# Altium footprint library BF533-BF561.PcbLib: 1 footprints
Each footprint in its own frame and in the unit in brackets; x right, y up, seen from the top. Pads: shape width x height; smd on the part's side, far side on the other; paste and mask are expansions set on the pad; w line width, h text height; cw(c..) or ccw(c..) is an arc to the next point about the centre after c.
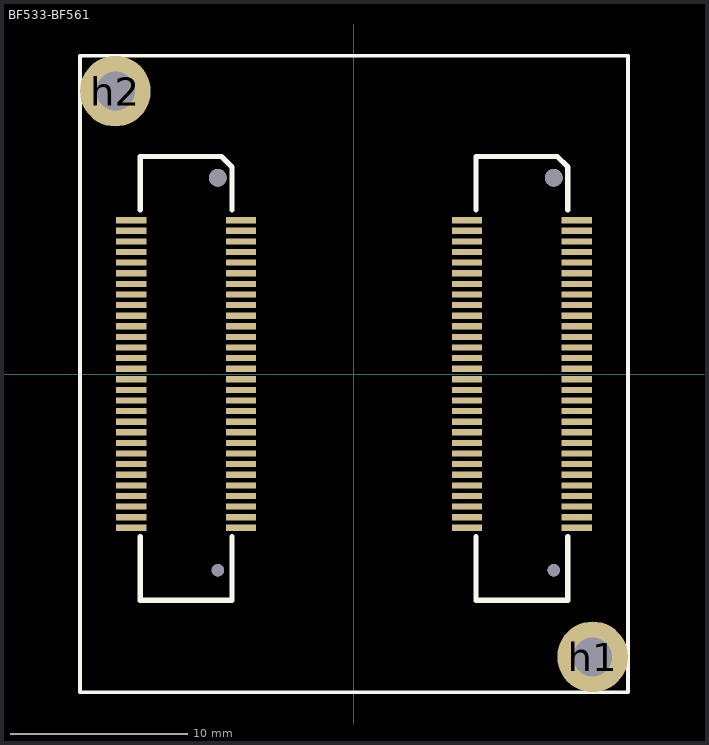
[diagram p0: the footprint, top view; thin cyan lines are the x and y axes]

## BF533-BF561 [mm] "Blackfin Board with Harwin Connectors"
height 5
pads (126):
  rect 1.7x0.35 smd paste-0.025: 1(-6.4,8.7) 2(-6.4,8.1) 3(-6.4,7.5) 4(-6.4,6.9) 5(-6.4,6.3) 6(-6.4,5.7) 7(-6.4,5.1) 8(-6.4,4.5) 9(-6.4,3.9) 10(-6.4,3.3) 11(-6.4,2.7) 12(-6.4,2.1) 13(-6.4,1.5) 14(-6.4,0.9) 15(-6.4,0.3) 16(-6.4,-0.3) 17(-6.4,-0.9) 18(-6.4,-1.5) 19(-6.4,-2.1) 20(-6.4,-2.7) 21(-6.4,-3.3) 22(-6.4,-3.9) 23(-6.4,-4.5) 24(-6.4,-5.1) 25(-6.4,-5.7) 26(-6.4,-6.3) 27(-6.4,-6.9) 28(-6.4,-7.5) 29(-6.4,-8.1) 30(-6.4,-8.7) 31(-12.6,-8.7) 32(-12.6,-8.1) 33(-12.6,-7.5) 34(-12.6,-6.9) 35(-12.6,-6.3) 36(-12.6,-5.7) 37(-12.6,-5.1) 38(-12.6,-4.5) 39(-12.6,-3.9) 40(-12.6,-3.3) 41(-12.6,-2.7) 42(-12.6,-2.1) 43(-12.6,-1.5) 44(-12.6,-0.9) 45(-12.6,-0.3) 46(-12.6,0.3) 47(-12.6,0.9) 48(-12.6,1.5) 49(-12.6,2.1) 50(-12.6,2.7) 51(-12.6,3.3) 52(-12.6,3.9) 53(-12.6,4.5) 54(-12.6,5.1) 55(-12.6,5.7) 56(-12.6,6.3) 57(-12.6,6.9) 58(-12.6,7.5) 59(-12.6,8.1) 60(-12.6,8.7) 61(12.6,8.7) 62(12.6,8.1) 63(12.6,7.5) 64(12.6,6.9) 65(12.6,6.3) 66(12.6,5.7) 67(12.6,5.1) 68(12.6,4.5) 69(12.6,3.9) 70(12.6,3.3) 71(12.6,2.7) 72(12.6,2.1) 73(12.6,1.5) 74(12.6,0.9) 75(12.6,0.3) 76(12.6,-0.3) 77(12.6,-0.9) 78(12.6,-1.5) 79(12.6,-2.1) 80(12.6,-2.7) 81(12.6,-3.3) 82(12.6,-3.9) 83(12.6,-4.5) 84(12.6,-5.1) 85(12.6,-5.7) 86(12.6,-6.3) 87(12.6,-6.9) 88(12.6,-7.5) 89(12.6,-8.1) 90(12.6,-8.7) 91(6.4,-8.7) 92(6.4,-8.1) 93(6.4,-7.5) 94(6.4,-6.9) 95(6.4,-6.3) 96(6.4,-5.7) 97(6.4,-5.1) 98(6.4,-4.5) 99(6.4,-3.9) 100(6.4,-3.3) 101(6.4,-2.7) 102(6.4,-2.1) 103(6.4,-1.5) 104(6.4,-0.9) 105(6.4,-0.3) 106(6.4,0.3) 107(6.4,0.9) 108(6.4,1.5) 109(6.4,2.1) 110(6.4,2.7) 111(6.4,3.3) 112(6.4,3.9) 113(6.4,4.5) 114(6.4,5.1) 115(6.4,5.7) 116(6.4,6.3) 117(6.4,6.9) 118(6.4,7.5) 119(6.4,8.1) 120(6.4,8.7)
  round 4 / inner round 2.5 / far side round 4 hole 2.2: h1(13.5,-16) h2(-13.5,16)
  round 1 hole 1 unplated: Hole1(-7.7,11.1) Hole1(11.3,11.1)
  round 0.7 hole 0.7 unplated: Hole2(-7.7,-11.1) Hole2(11.3,-11.1)
Top Overlay:
  lines w0.2: -15.5,-18 15.5,-18 15.5,18 -15.5,18 -15.5,-18
  lines w0.3: -12.1,-9.2 -12.1,-12.8 -6.9,-12.8 -6.9,-9.2 ; -12.1,9.3 -12.1,12.3 -7.5,12.3 -6.9,11.7 -6.9,9.3 ; 6.9,-9.2 6.9,-12.8 12.1,-12.8 12.1,-9.2 ; 6.9,9.3 6.9,12.3 11.5,12.3 12.1,11.7 12.1,9.3
3D body: height 2.2, standoff 0.1, extent 7.925,8.575 8.125,8.825
3D body: height 2.2, standoff 0.1, extent 7.925,7.975 8.125,8.225
3D body: height 2.2, standoff 0.1, extent 7.925,6.775 8.125,7.025
3D body: height 2.2, standoff 0.1, extent 7.925,7.375 8.125,7.625
3D body: height 2.2, standoff 0.1, extent 7.925,4.975 8.125,5.225
3D body: height 2.2, standoff 0.1, extent 7.925,4.375 8.125,4.625
3D body: height 2.2, standoff 0.1, extent 7.925,5.575 8.125,5.825
3D body: height 2.2, standoff 0.1, extent 7.925,6.175 8.125,6.425
3D body: height 2.2, standoff 0.1, extent 7.925,2.575 8.125,2.825
3D body: height 2.2, standoff 0.1, extent 7.925,1.975 8.125,2.225
3D body: height 2.2, standoff 0.1, extent 7.925,3.175 8.125,3.425
3D body: height 2.2, standoff 0.1, extent 7.925,3.775 8.125,4.025
3D body: height 2.2, standoff 0.1, extent 7.925,0.175 8.125,0.425
3D body: height 2.2, standoff 0.1, extent 7.925,-0.425 8.125,-0.175
3D body: height 2.2, standoff 0.1, extent 7.925,0.775 8.125,1.025
3D body: height 2.2, standoff 0.1, extent 7.925,1.375 8.125,1.625
3D body: height 2.2, standoff 0.1, extent 7.925,-2.225 8.125,-1.975
3D body: height 2.2, standoff 0.1, extent 7.925,-2.825 8.125,-2.575
3D body: height 2.2, standoff 0.1, extent 7.925,-1.625 8.125,-1.375
3D body: height 2.2, standoff 0.1, extent 7.925,-1.025 8.125,-0.775
3D body: height 2.2, standoff 0.1, extent 7.925,-4.625 8.125,-4.375
3D body: height 2.2, standoff 0.1, extent 7.925,-5.225 8.125,-4.975
3D body: height 2.2, standoff 0.1, extent 7.925,-4.025 8.125,-3.775
3D body: height 2.2, standoff 0.1, extent 7.925,-3.425 8.125,-3.175
3D body: height 2.2, standoff 0.1, extent 7.925,-7.025 8.125,-6.775
3D body: height 2.2, standoff 0.1, extent 7.925,-7.625 8.125,-7.375
3D body: height 2.2, standoff 0.1, extent 7.925,-6.425 8.125,-6.175
3D body: height 2.2, standoff 0.1, extent 7.925,-5.825 8.125,-5.575
3D body: height 2.2, standoff 0.1, extent 7.925,-8.825 8.125,-8.575
3D body: height 0.2, standoff 0, extent 6,-8.825 8.125,-8.575
3D body: height 2.2, standoff 0.1, extent 7.925,-8.225 8.125,-7.975
3D body: height 0.2, standoff 0, extent 6,-8.225 8.125,-7.975
3D body: height 0.2, standoff 0, extent 6,-7.625 8.125,-7.375
3D body: height 0.2, standoff 0, extent 6,-7.025 8.125,-6.775
3D body: height 0.2, standoff 0, extent 6,-6.425 8.125,-6.175
3D body: height 0.2, standoff 0, extent 6,-3.425 8.125,-3.175
3D body: height 0.2, standoff 0, extent 6,-4.025 8.125,-3.775
3D body: height 0.2, standoff 0, extent 6,-4.625 8.125,-4.375
3D body: height 0.2, standoff 0, extent 6,-5.225 8.125,-4.975
3D body: height 0.2, standoff 0, extent 6,-5.825 8.125,-5.575
3D body: height 0.2, standoff 0, extent 6,-0.425 8.125,-0.175
3D body: height 0.2, standoff 0, extent 6,-1.025 8.125,-0.775
3D body: height 0.2, standoff 0, extent 6,-1.625 8.125,-1.375
3D body: height 0.2, standoff 0, extent 6,-2.225 8.125,-1.975
3D body: height 0.2, standoff 0, extent 6,-2.825 8.125,-2.575
3D body: height 0.2, standoff 0, extent 6,2.575 8.125,2.825
3D body: height 0.2, standoff 0, extent 6,1.975 8.125,2.225
3D body: height 0.2, standoff 0, extent 6,1.375 8.125,1.625
3D body: height 0.2, standoff 0, extent 6,0.775 8.125,1.025
3D body: height 0.2, standoff 0, extent 6,0.175 8.125,0.425
3D body: height 0.2, standoff 0, extent 6,5.575 8.125,5.825
3D body: height 0.2, standoff 0, extent 6,4.975 8.125,5.225
3D body: height 0.2, standoff 0, extent 6,4.375 8.125,4.625
3D body: height 0.2, standoff 0, extent 6,3.775 8.125,4.025
3D body: height 0.2, standoff 0, extent 6,3.175 8.125,3.425
3D body: height 0.2, standoff 0, extent 6,8.575 8.125,8.825
3D body: height 0.2, standoff 0, extent 6,7.975 8.125,8.225
3D body: height 0.2, standoff 0, extent 6,7.375 8.125,7.625
3D body: height 0.2, standoff 0, extent 6,6.775 8.125,7.025
3D body: height 0.2, standoff 0, extent 6,6.175 8.125,6.425
3D body: height 0.5, standoff 0.1, extent 6.9,-12.8 12.1,12.3
3D body: height 2.25, standoff 0.1, extent 7.95,-9.65 11.05,9.65
3D body: height 2.25, standoff 0.1, extent 6.9,-12.8 12.1,12.3
3D body: height 0.2, standoff 0, extent 10.875,-6.425 13,-6.175
3D body: height 0.2, standoff 0, extent 10.875,-7.025 13,-6.775
3D body: height 0.2, standoff 0, extent 10.875,-7.625 13,-7.375
3D body: height 0.2, standoff 0, extent 10.875,-8.225 13,-7.975
3D body: height 0.2, standoff 0, extent 10.875,-8.825 13,-8.575
3D body: height 0.2, standoff 0, extent 10.875,-3.425 13,-3.175
3D body: height 0.2, standoff 0, extent 10.875,-4.025 13,-3.775
3D body: height 0.2, standoff 0, extent 10.875,-4.625 13,-4.375
3D body: height 0.2, standoff 0, extent 10.875,-5.225 13,-4.975
3D body: height 0.2, standoff 0, extent 10.875,-5.825 13,-5.575
3D body: height 0.2, standoff 0, extent 10.875,-0.425 13,-0.175
3D body: height 0.2, standoff 0, extent 10.875,-1.025 13,-0.775
3D body: height 0.2, standoff 0, extent 10.875,-1.625 13,-1.375
3D body: height 0.2, standoff 0, extent 10.875,-2.225 13,-1.975
3D body: height 0.2, standoff 0, extent 10.875,-2.825 13,-2.575
3D body: height 0.2, standoff 0, extent 10.875,2.575 13,2.825
3D body: height 0.2, standoff 0, extent 10.875,1.975 13,2.225
3D body: height 0.2, standoff 0, extent 10.875,1.375 13,1.625
3D body: height 0.2, standoff 0, extent 10.875,0.775 13,1.025
3D body: height 0.2, standoff 0, extent 10.875,0.175 13,0.425
3D body: height 0.2, standoff 0, extent 10.875,5.575 13,5.825
3D body: height 0.2, standoff 0, extent 10.875,4.975 13,5.225
3D body: height 0.2, standoff 0, extent 10.875,4.375 13,4.625
3D body: height 0.2, standoff 0, extent 10.875,3.775 13,4.025
3D body: height 0.2, standoff 0, extent 10.875,3.175 13,3.425
3D body: height 0.2, standoff 0, extent 10.875,6.175 13,6.425
3D body: height 0.2, standoff 0, extent 10.875,6.775 13,7.025
3D body: height 0.2, standoff 0, extent 10.875,7.375 13,7.625
3D body: height 0.2, standoff 0, extent 10.875,7.975 13,8.225
3D body: height 0.25, standoff -0.75, extent 10.852,10.654 11.75,11.55
3D body: height 0.25, standoff -0.75, extent 11.001,-11.398 11.6,-10.8
3D body: height 2.2, standoff 0.1, extent 10.875,7.975 11.075,8.225
3D body: height 0.2, standoff 0, extent 10.875,8.575 13,8.825
3D body: height 2.2, standoff 0.1, extent 10.875,8.575 11.075,8.825
3D body: height 2.2, standoff 0.1, extent 10.875,5.575 11.075,5.825
3D body: height 2.2, standoff 0.1, extent 10.875,6.175 11.075,6.425
3D body: height 2.2, standoff 0.1, extent 10.875,7.375 11.075,7.625
3D body: height 2.2, standoff 0.1, extent 10.875,6.775 11.075,7.025
3D body: height 2.2, standoff 0.1, extent 10.875,3.175 11.075,3.425
3D body: height 2.2, standoff 0.1, extent 10.875,3.775 11.075,4.025
3D body: height 2.2, standoff 0.1, extent 10.875,4.975 11.075,5.225
3D body: height 2.2, standoff 0.1, extent 10.875,4.375 11.075,4.625
3D body: height 2.2, standoff 0.1, extent 10.875,0.775 11.075,1.025
3D body: height 2.2, standoff 0.1, extent 10.875,1.375 11.075,1.625
3D body: height 2.2, standoff 0.1, extent 10.875,2.575 11.075,2.825
3D body: height 2.2, standoff 0.1, extent 10.875,1.975 11.075,2.225
3D body: height 2.2, standoff 0.1, extent 10.875,-1.625 11.075,-1.375
3D body: height 2.2, standoff 0.1, extent 10.875,-1.025 11.075,-0.775
3D body: height 2.2, standoff 0.1, extent 10.875,0.175 11.075,0.425
3D body: height 2.2, standoff 0.1, extent 10.875,-0.425 11.075,-0.175
3D body: height 2.2, standoff 0.1, extent 10.875,-4.025 11.075,-3.775
3D body: height 2.2, standoff 0.1, extent 10.875,-3.425 11.075,-3.175
3D body: height 2.2, standoff 0.1, extent 10.875,-2.225 11.075,-1.975
3D body: height 2.2, standoff 0.1, extent 10.875,-2.825 11.075,-2.575
3D body: height 2.2, standoff 0.1, extent 10.875,-6.425 11.075,-6.175
3D body: height 2.2, standoff 0.1, extent 10.875,-5.825 11.075,-5.575
3D body: height 2.2, standoff 0.1, extent 10.875,-4.625 11.075,-4.375
3D body: height 2.2, standoff 0.1, extent 10.875,-5.225 11.075,-4.975
3D body: height 2.2, standoff 0.1, extent 10.875,-7.625 11.075,-7.375
3D body: height 2.2, standoff 0.1, extent 10.875,-7.025 11.075,-6.775
3D body: height 2.2, standoff 0.1, extent 10.875,-8.225 11.075,-7.975
3D body: height 2.2, standoff 0.1, extent 10.875,-8.825 11.075,-8.575
3D body: height 2.2, standoff 0.1, extent -11.075,8.575 -10.875,8.825
3D body: height 2.2, standoff 0.1, extent -11.075,7.975 -10.875,8.225
3D body: height 2.2, standoff 0.1, extent -11.075,6.775 -10.875,7.025
3D body: height 2.2, standoff 0.1, extent -11.075,7.375 -10.875,7.625
3D body: height 2.2, standoff 0.1, extent -11.075,4.975 -10.875,5.225
3D body: height 2.2, standoff 0.1, extent -11.075,4.375 -10.875,4.625
3D body: height 2.2, standoff 0.1, extent -11.075,5.575 -10.875,5.825
3D body: height 2.2, standoff 0.1, extent -11.075,6.175 -10.875,6.425
3D body: height 2.2, standoff 0.1, extent -11.075,2.575 -10.875,2.825
3D body: height 2.2, standoff 0.1, extent -11.075,1.975 -10.875,2.225
3D body: height 2.2, standoff 0.1, extent -11.075,3.175 -10.875,3.425
3D body: height 2.2, standoff 0.1, extent -11.075,3.775 -10.875,4.025
3D body: height 2.2, standoff 0.1, extent -11.075,0.175 -10.875,0.425
3D body: height 2.2, standoff 0.1, extent -11.075,-0.425 -10.875,-0.175
3D body: height 2.2, standoff 0.1, extent -11.075,0.775 -10.875,1.025
3D body: height 2.2, standoff 0.1, extent -11.075,1.375 -10.875,1.625
3D body: height 2.2, standoff 0.1, extent -11.075,-2.225 -10.875,-1.975
3D body: height 2.2, standoff 0.1, extent -11.075,-2.825 -10.875,-2.575
3D body: height 2.2, standoff 0.1, extent -11.075,-1.625 -10.875,-1.375
3D body: height 2.2, standoff 0.1, extent -11.075,-1.025 -10.875,-0.775
3D body: height 2.2, standoff 0.1, extent -11.075,-4.625 -10.875,-4.375
3D body: height 2.2, standoff 0.1, extent -11.075,-5.225 -10.875,-4.975
3D body: height 2.2, standoff 0.1, extent -11.075,-4.025 -10.875,-3.775
3D body: height 2.2, standoff 0.1, extent -11.075,-3.425 -10.875,-3.175
3D body: height 2.2, standoff 0.1, extent -11.075,-7.025 -10.875,-6.775
3D body: height 2.2, standoff 0.1, extent -11.075,-7.625 -10.875,-7.375
3D body: height 2.2, standoff 0.1, extent -11.075,-6.425 -10.875,-6.175
3D body: height 2.2, standoff 0.1, extent -11.075,-5.825 -10.875,-5.575
3D body: height 2.2, standoff 0.1, extent -11.075,-8.825 -10.875,-8.575
3D body: height 0.2, standoff 0, extent -13,-8.825 -10.875,-8.575
3D body: height 2.2, standoff 0.1, extent -11.075,-8.225 -10.875,-7.975
3D body: height 0.2, standoff 0, extent -13,-8.225 -10.875,-7.975
3D body: height 0.2, standoff 0, extent -13,-7.625 -10.875,-7.375
3D body: height 0.2, standoff 0, extent -13,-7.025 -10.875,-6.775
3D body: height 0.2, standoff 0, extent -13,-6.425 -10.875,-6.175
3D body: height 0.2, standoff 0, extent -13,-3.425 -10.875,-3.175
3D body: height 0.2, standoff 0, extent -13,-4.025 -10.875,-3.775
3D body: height 0.2, standoff 0, extent -13,-4.625 -10.875,-4.375
3D body: height 0.2, standoff 0, extent -13,-5.225 -10.875,-4.975
3D body: height 0.2, standoff 0, extent -13,-5.825 -10.875,-5.575
3D body: height 0.2, standoff 0, extent -13,-0.425 -10.875,-0.175
3D body: height 0.2, standoff 0, extent -13,-1.025 -10.875,-0.775
3D body: height 0.2, standoff 0, extent -13,-1.625 -10.875,-1.375
3D body: height 0.2, standoff 0, extent -13,-2.225 -10.875,-1.975
3D body: height 0.2, standoff 0, extent -13,-2.825 -10.875,-2.575
3D body: height 0.2, standoff 0, extent -13,2.575 -10.875,2.825
3D body: height 0.2, standoff 0, extent -13,1.975 -10.875,2.225
3D body: height 0.2, standoff 0, extent -13,1.375 -10.875,1.625
3D body: height 0.2, standoff 0, extent -13,0.775 -10.875,1.025
3D body: height 0.2, standoff 0, extent -13,0.175 -10.875,0.425
3D body: height 0.2, standoff 0, extent -13,5.575 -10.875,5.825
3D body: height 0.2, standoff 0, extent -13,4.975 -10.875,5.225
3D body: height 0.2, standoff 0, extent -13,4.375 -10.875,4.625
3D body: height 0.2, standoff 0, extent -13,3.775 -10.875,4.025
3D body: height 0.2, standoff 0, extent -13,3.175 -10.875,3.425
3D body: height 0.2, standoff 0, extent -13,8.575 -10.875,8.825
3D body: height 0.2, standoff 0, extent -13,7.975 -10.875,8.225
3D body: height 0.2, standoff 0, extent -13,7.375 -10.875,7.625
3D body: height 0.2, standoff 0, extent -13,6.775 -10.875,7.025
3D body: height 0.2, standoff 0, extent -13,6.175 -10.875,6.425
3D body: height 0.5, standoff 0.1, extent -12.1,-12.8 -6.9,12.3
3D body: height 2.25, standoff 0.1, extent -11.05,-9.65 -7.95,9.65
3D body: height 2.25, standoff 0.1, extent -12.1,-12.8 -6.9,12.3
3D body: height 0.2, standoff 0, extent -8.125,-6.425 -6,-6.175
3D body: height 0.2, standoff 0, extent -8.125,-7.025 -6,-6.775
3D body: height 0.2, standoff 0, extent -8.125,-7.625 -6,-7.375
3D body: height 0.2, standoff 0, extent -8.125,-8.225 -6,-7.975
3D body: height 0.2, standoff 0, extent -8.125,-8.825 -6,-8.575
3D body: height 0.2, standoff 0, extent -8.125,-3.425 -6,-3.175
3D body: height 0.2, standoff 0, extent -8.125,-4.025 -6,-3.775
3D body: height 0.2, standoff 0, extent -8.125,-4.625 -6,-4.375
3D body: height 0.2, standoff 0, extent -8.125,-5.225 -6,-4.975
3D body: height 0.2, standoff 0, extent -8.125,-5.825 -6,-5.575
3D body: height 0.2, standoff 0, extent -8.125,-0.425 -6,-0.175
3D body: height 0.2, standoff 0, extent -8.125,-1.025 -6,-0.775
3D body: height 0.2, standoff 0, extent -8.125,-1.625 -6,-1.375
3D body: height 0.2, standoff 0, extent -8.125,-2.225 -6,-1.975
3D body: height 0.2, standoff 0, extent -8.125,-2.825 -6,-2.575
3D body: height 0.2, standoff 0, extent -8.125,2.575 -6,2.825
3D body: height 0.2, standoff 0, extent -8.125,1.975 -6,2.225
3D body: height 0.2, standoff 0, extent -8.125,1.375 -6,1.625
3D body: height 0.2, standoff 0, extent -8.125,0.775 -6,1.025
3D body: height 0.2, standoff 0, extent -8.125,0.175 -6,0.425
3D body: height 0.2, standoff 0, extent -8.125,5.575 -6,5.825
3D body: height 0.2, standoff 0, extent -8.125,4.975 -6,5.225
3D body: height 0.2, standoff 0, extent -8.125,4.375 -6,4.625
3D body: height 0.2, standoff 0, extent -8.125,3.775 -6,4.025
3D body: height 0.2, standoff 0, extent -8.125,3.175 -6,3.425
3D body: height 0.2, standoff 0, extent -8.125,6.175 -6,6.425
3D body: height 0.2, standoff 0, extent -8.125,6.775 -6,7.025
3D body: height 0.2, standoff 0, extent -8.125,7.375 -6,7.625
3D body: height 0.2, standoff 0, extent -8.125,7.975 -6,8.225
3D body: height 0.25, standoff -0.75, extent -8.148,10.654 -7.25,11.55
3D body: height 0.25, standoff -0.75, extent -7.999,-11.398 -7.4,-10.8
3D body: height 2.2, standoff 0.1, extent -8.125,7.975 -7.925,8.225
3D body: height 0.2, standoff 0, extent -8.125,8.575 -6,8.825
3D body: height 2.2, standoff 0.1, extent -8.125,8.575 -7.925,8.825
3D body: height 2.2, standoff 0.1, extent -8.125,5.575 -7.925,5.825
3D body: height 2.2, standoff 0.1, extent -8.125,6.175 -7.925,6.425
3D body: height 2.2, standoff 0.1, extent -8.125,7.375 -7.925,7.625
3D body: height 2.2, standoff 0.1, extent -8.125,6.775 -7.925,7.025
3D body: height 2.2, standoff 0.1, extent -8.125,3.175 -7.925,3.425
3D body: height 2.2, standoff 0.1, extent -8.125,3.775 -7.925,4.025
3D body: height 2.2, standoff 0.1, extent -8.125,4.975 -7.925,5.225
3D body: height 2.2, standoff 0.1, extent -8.125,4.375 -7.925,4.625
3D body: height 2.2, standoff 0.1, extent -8.125,0.775 -7.925,1.025
3D body: height 2.2, standoff 0.1, extent -8.125,1.375 -7.925,1.625
3D body: height 2.2, standoff 0.1, extent -8.125,2.575 -7.925,2.825
3D body: height 2.2, standoff 0.1, extent -8.125,1.975 -7.925,2.225
3D body: height 2.2, standoff 0.1, extent -8.125,-1.625 -7.925,-1.375
3D body: height 2.2, standoff 0.1, extent -8.125,-1.025 -7.925,-0.775
3D body: height 2.2, standoff 0.1, extent -8.125,0.175 -7.925,0.425
3D body: height 2.2, standoff 0.1, extent -8.125,-0.425 -7.925,-0.175
3D body: height 2.2, standoff 0.1, extent -8.125,-4.025 -7.925,-3.775
3D body: height 2.2, standoff 0.1, extent -8.125,-3.425 -7.925,-3.175
3D body: height 2.2, standoff 0.1, extent -8.125,-2.225 -7.925,-1.975
3D body: height 2.2, standoff 0.1, extent -8.125,-2.825 -7.925,-2.575
3D body: height 2.2, standoff 0.1, extent -8.125,-6.425 -7.925,-6.175
3D body: height 2.2, standoff 0.1, extent -8.125,-5.825 -7.925,-5.575
3D body: height 2.2, standoff 0.1, extent -8.125,-4.625 -7.925,-4.375
3D body: height 2.2, standoff 0.1, extent -8.125,-5.225 -7.925,-4.975
3D body: height 2.2, standoff 0.1, extent -8.125,-7.625 -7.925,-7.375
3D body: height 2.2, standoff 0.1, extent -8.125,-7.025 -7.925,-6.775
3D body: height 2.2, standoff 0.1, extent -8.125,-8.225 -7.925,-7.975
3D body: height 2.2, standoff 0.1, extent -8.125,-8.825 -7.925,-8.575
3D body: height 6.01, standoff 0.46, extent -15.5,-18 15.5,18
